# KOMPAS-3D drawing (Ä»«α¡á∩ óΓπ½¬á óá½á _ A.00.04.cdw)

Views: Спереди 1, Спереди, Проекционный вид 2, Проекционный вид 3, Проекционный вид 4, Проекционный вид 5, Проекционный вид 6, Изометрия XYZ 7, Изометрия XYZ, Разрез А-А
Referenced files in C:\Users\s.slezkin\Desktop\Раскатчик арок 2\: Опорная втулка вала _ A.00.04.m3d, Опорная втулка вала _ A.00.04.cdw
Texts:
  Опорная втулка вала
  http://vk.com/sergey_krd
  Опорная втулка
  вала
  Сталь 40Х  ГОСТ 4543-71
Dimensions and other numbers on the sheet: 50; 18; 1; 3; 21; 8,5; 25; 8; 15; 1:1; 0,08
